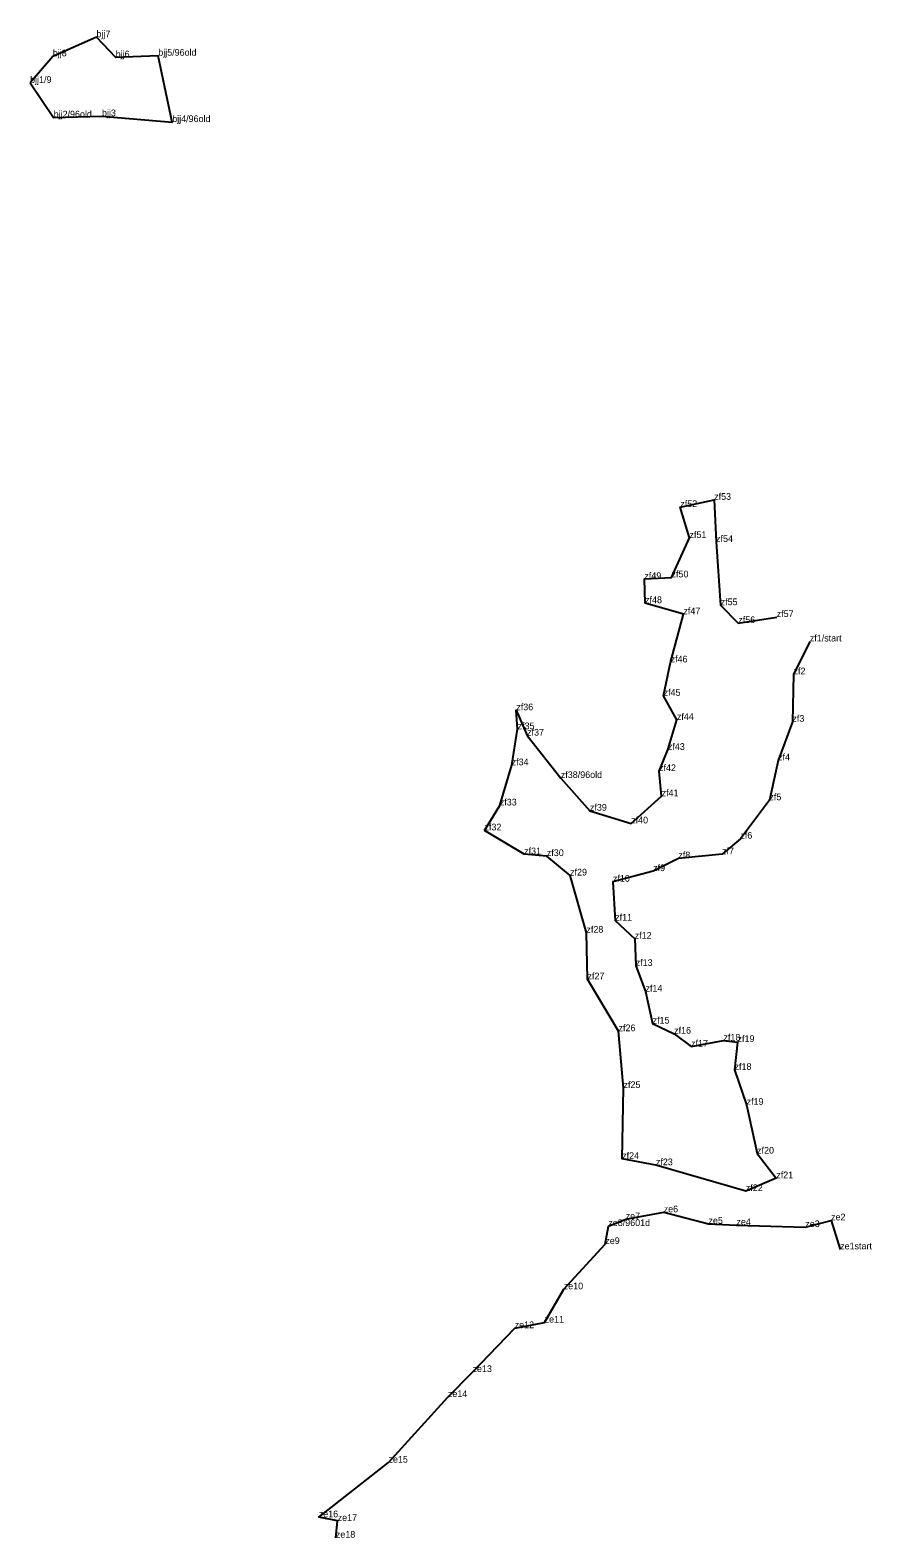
# Model space of a CAD drawing. Extents: x 2072529 to 2267990, y 436423 to 470008.
# Drawn here: x 2264819 to 2265575, y 441427 to 442781 of the extents above; entities that cross this region are included whole.
import ezdxf

# ---------------------------------------------------------------- set-up
doc = ezdxf.new("R2010")
doc.units = 0
doc.layers.add('Level 3', color=7, linetype='Continuous')
doc.layers.add('Old_Level_52', color=7, linetype='Continuous')

msp = doc.modelspace()

# ---------------------------------------------------------------- linework, layer by layer
at = {"layer": 'Level 3'}
for p, q in [((2264878.379, 442775.137), (2264878.379, 442775.137)), ((2264839.148, 442757.923), (2264839.148, 442757.923)), ((2264895.631, 442756.976), (2264895.631, 442756.976)), ((2264933.908, 442758.471), (2264933.908, 442758.471)), ((2264818.78, 442734.072), (2264818.78, 442734.072)), ((2264839.893, 442703.053), (2264839.893, 442703.053)), ((2264883.316, 442704.162), (2264883.316, 442704.162)), ((2264946.448, 442698.893), (2264946.448, 442698.893)), ((2265433.343, 442359.639), (2265433.343, 442359.639)), ((2265402.941, 442353.172), (2265402.941, 442353.172)), ((2265411.198, 442325.336), (2265411.198, 442325.336)), ((2265435.072, 442321.768), (2265435.072, 442321.768)), ((2265370.663, 442288.534), (2265370.663, 442288.534)), ((2265395.066, 442289.908), (2265395.066, 442289.908)), ((2265371.296, 442266.799), (2265371.296, 442266.799)), ((2265439.182, 442265.004), (2265439.182, 442265.004)), ((2265405.724, 442256.831), (2265405.724, 442256.831)), ((2265455.053, 442248.936), (2265455.053, 442248.936)), ((2265489.536, 442254.307), (2265489.536, 442254.307)), ((2265519.295, 442232.414), (2265519.295, 442232.414)), ((2265394.234, 442213.591), (2265394.234, 442213.591)), ((2265504.668, 442202.881), (2265504.668, 442202.881)), ((2265387.924, 442183.618), (2265387.924, 442183.618)), ((2265255.568, 442170.601), (2265255.568, 442170.601)), ((2265256.744, 442153.597), (2265256.744, 442153.597)), ((2265399.875, 442161.922), (2265399.875, 442161.922)), ((2265503.655, 442160.282), (2265503.655, 442160.282)), ((2265265.273, 442147.864), (2265265.273, 442147.864)), ((2265391.8, 442135.008), (2265391.8, 442135.008)), ((2265490.755, 442125.529), (2265490.755, 442125.529)), ((2265251.416, 442121.225), (2265251.416, 442121.225)), ((2265383.841, 442115.984), (2265383.841, 442115.984)), ((2265295.616, 442109.768), (2265295.616, 442109.768)), ((2265240.769, 442085.103), (2265240.769, 442085.103)), ((2265386.136, 442093.391), (2265386.136, 442093.391)), ((2265483.025, 442089.778), (2265483.025, 442089.778)), ((2265321.722, 442080.413), (2265321.722, 442080.413)), ((2265226.999, 442062.694), (2265226.999, 442062.694)), ((2265358.78, 442068.964), (2265358.78, 442068.964)), ((2265456.892, 442055.258), (2265456.892, 442055.258)), ((2265262.605, 442041.235), (2265262.605, 442041.235)), ((2265283.018, 442039.64), (2265283.018, 442039.64)), ((2265401.16, 442037.607), (2265401.16, 442037.607)), ((2265440.431, 442041.237), (2265440.431, 442041.237)), ((2265303.913, 442022.192), (2265303.913, 442022.192)), ((2265378.533, 442026.126), (2265378.533, 442026.126)), ((2265342.375, 442016.572), (2265342.375, 442016.572)), ((2265344.439, 441981.707), (2265344.439, 441981.707)), ((2265318.614, 441970.834), (2265318.614, 441970.834)), ((2265361.975, 441965.422), (2265361.975, 441965.422)), ((2265362.844, 441940.96), (2265362.844, 441940.96)), ((2265319.577, 441928.955), (2265319.577, 441928.955)), ((2265371.662, 441917.928), (2265371.662, 441917.928)), ((2265347.444, 441882.363), (2265347.444, 441882.363)), ((2265378.051, 441889.22), (2265378.051, 441889.22)), ((2265397.391, 441880.125), (2265397.391, 441880.125)), ((2265412.644, 441868.479), (2265412.644, 441868.479)), ((2265441.734, 441873.914), (2265441.734, 441873.914)), ((2265454.364, 441872.662), (2265454.364, 441872.662)), ((2265451.673, 441847.609), (2265451.673, 441847.609)), ((2265351.938, 441831.334), (2265351.938, 441831.334)), ((2265462.497, 441816.233), (2265462.497, 441816.233)), ((2265350.683, 441767.624), (2265350.683, 441767.624)), ((2265381.032, 441761.994), (2265381.032, 441761.994)), ((2265471.942, 441772.393), (2265471.942, 441772.393)), ((2265489.135, 441750.298), (2265489.135, 441750.298)), ((2265461.83, 441738.782), (2265461.83, 441738.782)), ((2265388.01, 441719.713), (2265388.01, 441719.713)), ((2265338.279, 441707.342), (2265338.279, 441707.342)), ((2265353.88, 441713.508), (2265353.88, 441713.508)), ((2265428.246, 441709.399), (2265428.246, 441709.399)), ((2265453.366, 441708.177), (2265453.366, 441708.177)), ((2265515.211, 441706.42), (2265515.211, 441706.42)), ((2265538.392, 441712.492), (2265538.392, 441712.492)), ((2265335.527, 441691.202), (2265335.527, 441691.202)), ((2265546.543, 441686.425), (2265546.543, 441686.425)), ((2265298.183, 441650.584), (2265298.183, 441650.584)), ((2265254.128, 441615.641), (2265254.128, 441615.641)), ((2265281.013, 441620.645), (2265281.013, 441620.645)), ((2265216.24, 441576.245), (2265216.24, 441576.245)), ((2265194.1, 441553.787), (2265194.1, 441553.787)), ((2265140.765, 441494.89), (2265140.765, 441494.89)), ((2265078.082, 441445.801), (2265078.082, 441445.801)), ((2265095.071, 441442.48), (2265095.071, 441442.48)), ((2265093.47, 441427.406), (2265093.47, 441427.406))]:
    msp.add_line(p, q, dxfattribs=at)
at = {"layer": 'Old_Level_52'}
msp.add_lwpolyline([(2264818.78, 442734.072), (2264839.893, 442703.053), (2264883.316, 442704.162), (2264946.448, 442698.893), (2264933.908, 442758.471), (2264895.631, 442756.976), (2264878.379, 442775.137), (2264839.148, 442757.923)], close=True, dxfattribs=at)
for points in [[(2265226.999, 442062.694), (2265240.769, 442085.103), (2265251.416, 442121.225), (2265256.744, 442153.597), (2265255.568, 442170.601), (2265265.273, 442147.864), (2265295.616, 442109.768), (2265321.722, 442080.413), (2265358.78, 442068.964), (2265386.136, 442093.391), (2265383.841, 442115.984), (2265391.8, 442135.008), (2265399.875, 442161.922), (2265387.924, 442183.618), (2265394.234, 442213.591), (2265405.724, 442256.831), (2265371.296, 442266.799), (2265370.663, 442288.534), (2265395.066, 442289.908), (2265411.198, 442325.336), (2265402.941, 442353.172), (2265433.343, 442359.639), (2265435.072, 442321.768), (2265439.182, 442265.004), (2265455.053, 442248.936), (2265489.536, 442254.307)], [(2265519.295, 442232.414), (2265504.668, 442202.881), (2265503.655, 442160.282), (2265490.755, 442125.529), (2265483.025, 442089.778), (2265456.892, 442055.258), (2265440.431, 442041.237), (2265401.16, 442037.607), (2265378.533, 442026.126), (2265342.375, 442016.572), (2265344.439, 441981.707), (2265361.975, 441965.422), (2265362.844, 441940.96), (2265371.662, 441917.928), (2265378.051, 441889.22), (2265397.391, 441880.125), (2265412.644, 441868.479), (2265441.734, 441873.914), (2265454.364, 441872.662), (2265451.673, 441847.609), (2265462.497, 441816.233), (2265471.942, 441772.393), (2265489.135, 441750.298), (2265461.83, 441738.782), (2265381.032, 441761.994), (2265350.683, 441767.624), (2265351.938, 441831.334), (2265347.444, 441882.363), (2265319.577, 441928.955), (2265318.614, 441970.834), (2265303.913, 442022.192), (2265283.018, 442039.64), (2265262.605, 442041.235), (2265226.999, 442062.694)], [(2265093.47, 441427.406), (2265095.071, 441442.48), (2265078.082, 441445.801), (2265140.765, 441494.89), (2265194.1, 441553.787), (2265216.24, 441576.245), (2265254.128, 441615.641), (2265281.013, 441620.645), (2265298.183, 441650.584), (2265335.527, 441691.202), (2265338.279, 441707.342), (2265353.88, 441713.508), (2265388.01, 441719.713), (2265428.246, 441709.399), (2265453.366, 441708.177), (2265515.211, 441706.42), (2265538.392, 441712.492), (2265546.543, 441686.425)]]:
    msp.add_lwpolyline(points, dxfattribs=at)

# ---------------------------------------------------------------- texts
for s, p in [('bjj7', (2264878.379, 442775.137)), ('bjj8', (2264839.148, 442757.923)), ('bjj6', (2264895.631, 442756.976)), ('bjj5/96old', (2264933.908, 442758.471)), ('bjj1/9', (2264818.78, 442734.072)), ('bjj2/96old', (2264839.893, 442703.053)), ('bjj3', (2264883.316, 442704.162)), ('bjj4/96old', (2264946.448, 442698.893)), ('zf52', (2265402.941, 442353.172)), ('zf53', (2265433.343, 442359.639)), ('zf51', (2265411.198, 442325.336)), ('zf54', (2265435.072, 442321.768)), ('zf49', (2265370.663, 442288.534)), ('zf50', (2265395.066, 442289.908)), ('zf48', (2265371.296, 442266.799)), ('zf47', (2265405.724, 442256.831)), ('zf55', (2265439.182, 442265.004)), ('zf56', (2265455.053, 442248.936)), ('zf57', (2265489.536, 442254.307)), ('zf1/start', (2265519.295, 442232.414)), ('zf46', (2265394.234, 442213.591)), ('zf2', (2265504.668, 442202.881)), ('zf45', (2265387.924, 442183.618)), ('zf36', (2265255.568, 442170.601)), ('zf44', (2265399.875, 442161.922)), ('zf3', (2265503.655, 442160.282)), ('zf35', (2265256.744, 442153.597)), ('zf37', (2265265.273, 442147.864)), ('zf43', (2265391.8, 442135.008)), ('zf34', (2265251.416, 442121.225)), ('zf4', (2265490.755, 442125.529)), ('zf38/96old', (2265295.616, 442109.768)), ('zf42', (2265383.841, 442115.984)), ('zf41', (2265386.136, 442093.391)), ('zf33', (2265240.769, 442085.103)), ('zf39', (2265321.722, 442080.413)), ('zf5', (2265483.025, 442089.778)), ('zf40', (2265358.78, 442068.964)), ('zf32', (2265226.999, 442062.694)), ('zf6', (2265456.892, 442055.258)), ('zf31', (2265262.605, 442041.235)), ('zf30', (2265283.018, 442039.64)), ('zf7', (2265440.431, 442041.237)), ('zf9', (2265378.533, 442026.126)), ('zf8', (2265401.16, 442037.607)), ('zf29', (2265303.913, 442022.192)), ('zf10', (2265342.375, 442016.572)), ('zf28', (2265318.614, 441970.834)), ('zf11', (2265344.439, 441981.707)), ('zf12', (2265361.975, 441965.422)), ('zf13', (2265362.844, 441940.96)), ('zf27', (2265319.577, 441928.955)), ('zf14', (2265371.662, 441917.928)), ('zf15', (2265378.051, 441889.22)), ('zf26', (2265347.444, 441882.363)), ('zf16', (2265397.391, 441880.125)), ('zf17', (2265412.644, 441868.479)), ('zf18', (2265441.734, 441873.914)), ('zf19', (2265454.364, 441872.662)), ('zf18', (2265451.673, 441847.609)), ('zf25', (2265351.938, 441831.334)), ('zf19', (2265462.497, 441816.233)), ('zf24', (2265350.683, 441767.624)), ('zf20', (2265471.942, 441772.393)), ('zf23', (2265381.032, 441761.994)), ('zf21', (2265489.135, 441750.298)), ('zf22', (2265461.83, 441738.782)), ('ze7', (2265353.88, 441713.508)), ('ze6', (2265388.01, 441719.713)), ('ze8/9601d', (2265338.279, 441707.342)), ('ze5', (2265428.246, 441709.399)), ('ze4', (2265453.366, 441708.177)), ('ze3', (2265515.211, 441706.42)), ('ze2', (2265538.392, 441712.492)), ('ze9', (2265335.527, 441691.202)), ('ze1start', (2265546.543, 441686.425)), ('ze10', (2265298.183, 441650.584)), ('ze11', (2265281.013, 441620.645)), ('ze12', (2265254.128, 441615.641)), ('ze13', (2265216.24, 441576.245)), ('ze14', (2265194.1, 441553.787)), ('ze15', (2265140.765, 441494.89)), ('ze16', (2265078.082, 441445.801)), ('ze17', (2265095.071, 441442.48)), ('ze18', (2265093.47, 441427.406))]:
    msp.add_text(s, height=6).set_placement(p)

doc.saveas('drawing.dxf')
